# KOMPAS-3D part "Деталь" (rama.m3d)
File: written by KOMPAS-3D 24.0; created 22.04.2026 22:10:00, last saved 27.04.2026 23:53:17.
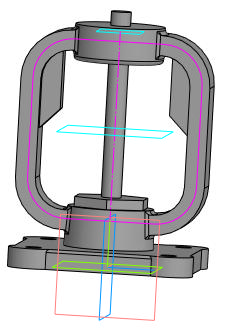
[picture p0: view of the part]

Document properties: Автор: mrdid; Полное имя файла: C:\Работа\ГОТОВЫЕ ИСХОДНИКИ\VSO2130M-F-S Клапан запорный сальниковый DN.ru Ду15-100 Ру40\исходные материалы\DN40\rama.m3d

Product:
- Part/product: Деталь
    Масса: 1.566924

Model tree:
1. Эскиз:2  (with: Ребро.Элемент выдавливания:14)
2. Элемент выдавливания:1
     Расстояние 1 = 10
3. Эскиз:3  (with: Грань.Элемент выдавливания:1, Ребро.Элемент выдавливания:1)
4. Элемент выдавливания:2
     Расстояние 2 = 10
5. Эскиз:4  (with: Грань.Элемент выдавливания:1)
6. Элемент выдавливания:3
     Угол 1 = -3
7. Эскиз:5  (with: Грань.Элемент выдавливания:3, Ребро.Элемент выдавливания:3)
8. Элемент выдавливания:4
9. Эскиз:23  (with: Грань.Элемент выдавливания:4, Ребро.Элемент выдавливания:4)
10. Элемент выдавливания:21  (labels: Деталь2; Грань.Твердое тело1)
     Расстояние 1 = 92.831
11. Эскиз:7  (with: Грань.Элемент выдавливания:4, Ребро.Элемент выдавливания:3)
12. Элемент выдавливания:6  (with: Грань.Элемент выдавливания:3)
     Расстояние 2 = 5
13. Смещенная плоскость:4  (labels: Деталь2; Грань.Твердое тело1)
     Расстояние = 10
14. Эскиз:24  (with: Ребро.Элемент выдавливания:3)
15. Элемент выдавливания:22
     Расстояние 1 = 3; Расстояние 2 = 15
16. Эскиз:25  (with: Ребро.Элемент выдавливания:3)
17. Эскиз:26  (with: Ребро.Элемент выдавливания:3)
18. Элемент по траектории:1
     Длина траектории = 315.326
19. Скругление:8  (with: Ребро.Элемент по траектории:1)
     Радиус = 2
20. Скругление:9  (with: Ребро.Элемент по траектории:1)
     Радиус = 2
21. Смещенная плоскость:5  (with: Грань.Элемент выдавливания:1)
22. Эскиз:27  (with: Вершина.Элемент по траектории:1)
23. Элемент выдавливания:23  (with: Грань.Элемент выдавливания:22)
     Расстояние 1 = 40.081; Смещение 1 = 5
24. Скругление:1  (with: Ребро.Элемент выдавливания:1)
     Радиус = 1.5
25. Скругление:10  (with: Ребро.Элемент выдавливания:22)
     Радиус = 2
26. Фаска:1  (with: Ребро.Элемент выдавливания:23)
     Угол = 45; Длина 1 = 10; Длина 2 = 10
27. Массив по концентрической сетке:1  (with: Элемент выдавливания:2, Эскиз:3)  (labels: Клапан запорный DN.ru Ду40 Ру40)  (4 pattern instances)
     Шаг 2 = 360

Expressions: DN/2; DN/4; H/4
Referenced files in C:\Работа\ГОТОВЫЕ ИСХОДНИКИ\VSO2130M-F-S Клапан запорный сальниковый DN.ru Ду15-100 Ру40\исходные материалы\DN40\: VSO2130M-F-S Клапан запорный DN.ru Ду40 Ру40.a3d
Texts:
  DN+5
  Ось Y.Начало координат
